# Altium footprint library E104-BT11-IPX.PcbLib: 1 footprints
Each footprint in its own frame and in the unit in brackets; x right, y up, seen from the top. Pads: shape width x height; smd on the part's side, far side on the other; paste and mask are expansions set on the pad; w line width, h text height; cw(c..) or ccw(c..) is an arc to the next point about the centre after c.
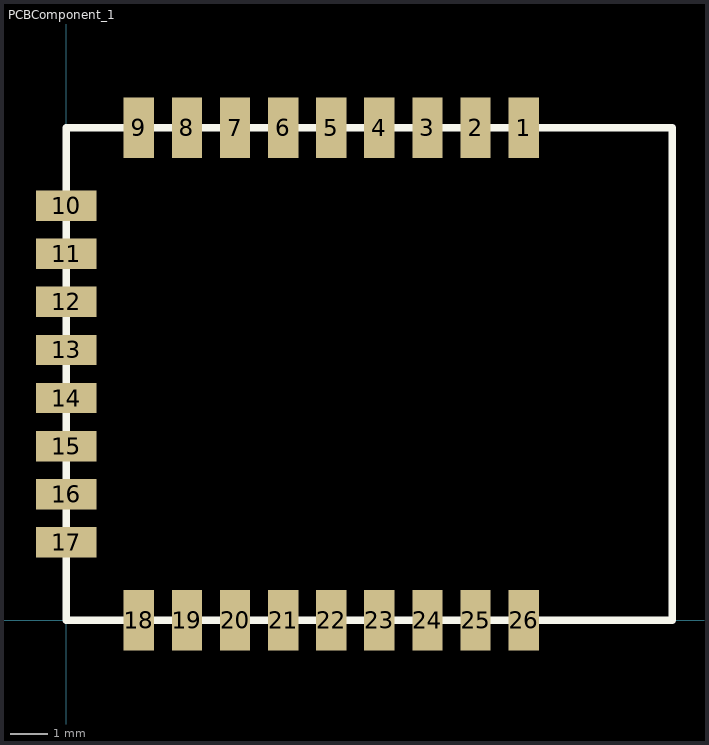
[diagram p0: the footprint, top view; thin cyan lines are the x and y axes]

## PCBComponent_1 [mm]
pads (26):
  rect 0.8x1.6 smd: 1(12.08,13) 2(10.81,13) 3(9.54,13) 4(8.27,13) 5(7,13) 6(5.73,13) 7(4.46,13) 8(3.19,13) 9(1.92,13) 18(1.92,0) 19(3.19,0) 20(4.46,0) 21(5.73,0) 22(7,0) 23(8.27,0) 24(9.54,0) 25(10.81,0) 26(12.08,0)
  rect 1.6x0.8 smd: 10(0,10.945) 11(0,9.675) 12(0,8.405) 13(0,7.135) 14(0,5.865) 15(0,4.595) 16(0,3.325) 17(0,2.055)
Top Overlay:
  lines w0.2: 0,0 16,0 16,13 0,13 0,0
